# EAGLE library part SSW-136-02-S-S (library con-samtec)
THROUGH-HOLE .025" SQ POST SOCKET Source: Samtec SSW.pdf
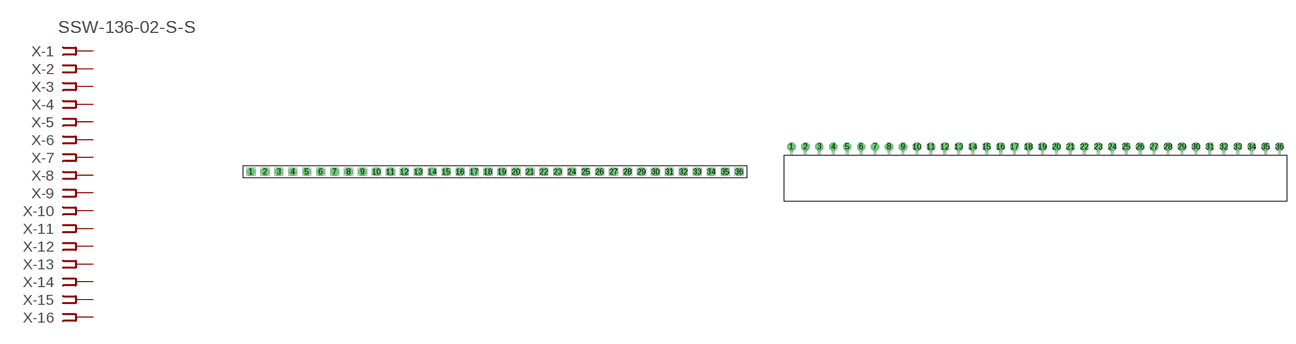
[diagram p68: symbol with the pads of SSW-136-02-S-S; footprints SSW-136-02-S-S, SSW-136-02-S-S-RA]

Designator prefix X; gates -1=FPINV -2=FPIN -3=FPIN -4=FPIN -5=FPIN -6=FPIN -7=FPIN -8=FPIN -9=FPIN -10=FPIN -11=FPIN -12=FPIN -13=FPIN -14=FPIN -15=FPIN -16=FPIN -17=FPIN -18=FPIN -19=FPIN -20=FPIN -21=FPIN -22=FPIN -23=FPIN -24=FPIN -25=FPIN -26=FPIN -27=FPIN -28=FPIN -29=FPIN -30=FPIN -31=FPIN -32=FPIN -33=FPIN -34=FPIN -35=FPIN -36=FPIN

## SSW-136-02-S-S (MPN: SSW-136-02-S-S; OC_FARNELL: unknown; OC_NEWARK: 11P9904)  [SSW-136-02-S-S]
1  -1:1  pas
2  -2:1  pas
3  -3:1  pas
4  -4:1  pas
5  -5:1  pas
6  -6:1  pas
7  -7:1  pas
8  -8:1  pas
9  -9:1  pas
10  -10:1  pas
11  -11:1  pas
12  -12:1  pas
13  -13:1  pas
14  -14:1  pas
15  -15:1  pas
16  -16:1  pas
17  -17:1  pas
18  -18:1  pas
19  -19:1  pas
20  -20:1  pas
21  -21:1  pas
22  -22:1  pas
23  -23:1  pas
24  -24:1  pas
25  -25:1  pas
26  -26:1  pas
27  -27:1  pas
28  -28:1  pas
29  -29:1  pas
30  -30:1  pas
31  -31:1  pas
32  -32:1  pas
33  -33:1  pas
34  -34:1  pas
35  -35:1  pas
36  -36:1  pas

## SSW-136-02-S-S-RA (MPN: SSW-136-02-S-S-RA; OC_FARNELL: unknown; OC_NEWARK: 11P9905)  [SSW-136-02-S-S-RA]
Pads as for SSW-136-02-S-S

## Footprint SSW-136-02-S-S (pad centres in mm)
THROUGH-HOLE .025" SQ POST SOCKET Source: Samtec SSW.pdf
drill 1 pad 1.5 octagon: 1 -44.45,0; 2 -41.91,0; 3 -39.37,0; 4 -36.83,0; 5 -34.29,0; 6 -31.75,0; 7 -29.21,0; 8 -26.67,0; 9 -24.13,0; 10 -21.59,0; 11 -19.05,0; 12 -16.51,0; 13 -13.97,0; 14 -11.43,0; 15 -8.89,0; 16 -6.35,0; 17 -3.81,0; 18 -1.27,0; 19 1.27,0; 20 3.81,0; 21 6.35,0; 22 8.89,0; 23 11.43,0; 24 13.97,0; 25 16.51,0; 26 19.05,0; 27 21.59,0; 28 24.13,0; 29 26.67,0; 30 29.21,0; 31 31.75,0; 32 34.29,0; 33 36.83,0; 34 39.37,0; 35 41.91,0; 36 44.45,0

## Footprint SSW-136-02-S-S-RA (pad centres in mm)
THROUGH-HOLE .025" SQ POST SOCKET Source: Samtec SSW.pdf
drill 1 pad 1.5 octagon: 1 -44.45,1.524; 2 -41.91,1.524; 3 -39.37,1.524; 4 -36.83,1.524; 5 -34.29,1.524; 6 -31.75,1.524; 7 -29.21,1.524; 8 -26.67,1.524; 9 -24.13,1.524; 10 -21.59,1.524; 11 -19.05,1.524; 12 -16.51,1.524; 13 -13.97,1.524; 14 -11.43,1.524; 15 -8.89,1.524; 16 -6.35,1.524; 17 -3.81,1.524; 18 -1.27,1.524; 19 1.27,1.524; 20 3.81,1.524; 21 6.35,1.524; 22 8.89,1.524; 23 11.43,1.524; 24 13.97,1.524; 25 16.51,1.524; 26 19.05,1.524; 27 21.59,1.524; 28 24.13,1.524; 29 26.67,1.524; 30 29.21,1.524; 31 31.75,1.524; 32 34.29,1.524; 33 36.83,1.524; 34 39.37,1.524; 35 41.91,1.524; 36 44.45,1.524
